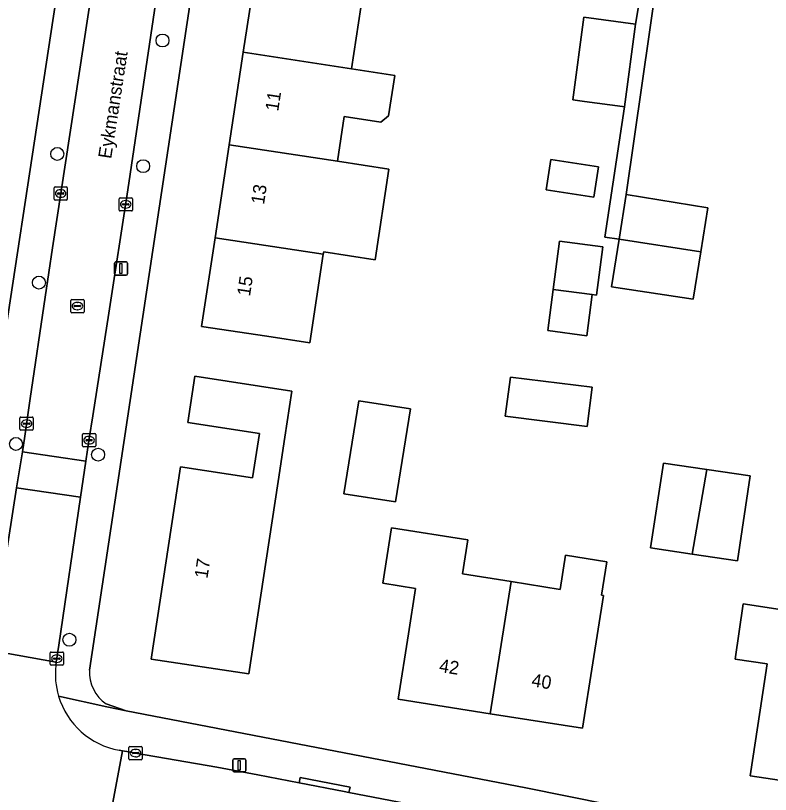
# Model space of a CAD drawing. Extents: x 161483 to 162250, y 379484 to 380833.
# Drawn here: x 161821 to 161877.9, y 380425.9 to 380484.6 of the extents above; entities that cross this region are included whole.
import ezdxf

# ---------------------------------------------------------------- set-up
doc = ezdxf.new("R2010")
doc.units = 0
for name, color, linetype in [('IMGEO_Boom', 7, 'Continuous'), ('IMGEO_Erf', 7, 'Continuous'), ('IMGEO_Kolk', 7, 'Continuous'), ('IMGEO_Lichtmast', 7, 'Continuous'), ('IMGEO_Openbare_ruimte_label', 7, 'Continuous'), ('IMGEO_Pand', 7, 'Continuous'), ('IMGEO_Pand_nummerreeks', 7, 'Continuous'), ('IMGEO_Rijbaan_lokaal_open', 7, 'Continuous'), ('IMGEO_Rioolput', 7, 'Continuous'), ('IMGEO_Voetpad_open', 7, 'Continuous')]:
    doc.layers.add(name, color=color, linetype=linetype)

msp = doc.modelspace()

# ---------------------------------------------------------------- linework, layer by layer
at = {"layer": 'IMGEO_Boom'}
for centre in [(161832.053, 380482.762), (161824.11, 380474.203), (161830.591, 380473.281), (161822.726, 380464.494), (161820.99, 380452.319), (161827.191, 380451.51), (161825.022, 380437.542)]:
    msp.add_circle(centre, 0.489, dxfattribs=at)
at = {"layer": 'IMGEO_Erf'}
for points in [[(161816.597, 380437.337), (161826.151, 380500)], [(161836.294, 380500), (161826.545, 380435.252)], [(161847.388, 380487.593), (161846.325, 380480.624), (161849.593, 380480.124), (161849.126, 380477.069), (161848.539, 380476.607), (161845.777, 380477.029), (161845.262, 380473.654), (161849.136, 380473.063), (161848.096, 380466.22), (161844.219, 380466.817), (161844.191, 380466.631), (161843.171, 380459.949), (161839.939, 380460.44), (161834.995, 380461.191), (161836.017, 380467.88), (161837.089, 380474.902), (161838.154, 380481.872), (161839.218, 380488.841)], [(161869.458, 380487.783), (161867.068, 380471.144), (161873.226, 380470.146), (161872.687, 380466.824), (161872.106, 380463.236), (161865.943, 380464.186), (161866.521, 380467.762), (161865.439, 380467.927), (161866.935, 380477.763), (161866.787, 380477.783), (161863.922, 380478.165), (161863.02, 380478.285), (161863.852, 380484.527), (161867.767, 380484.005), (161868.414, 380487.907)], [(161827.793, 380432.697), (161829.302, 380432.17), (161859.489, 380426.367), (161890.306, 380420.151)]]:
    msp.add_lwpolyline(points, dxfattribs=at)
for points in [[(161864.97, 380473.224), (161864.624, 380470.945), (161861.027, 380471.492), (161861.373, 380473.771)], [(161865.293, 380467.183), (161864.819, 380463.556), (161864.5, 380463.597), (161864.093, 380460.488), (161861.148, 380460.874), (161861.555, 380463.983), (161862.03, 380467.61)], [(161841.285, 380452.827), (161840.776, 380449.476), (161838.573, 380434.968), (161831.208, 380436.086), (161833.411, 380450.594), (161838.839, 380449.771), (161839.386, 380453.116), (161833.958, 380453.939), (161834.487, 380457.423), (161841.814, 380456.311)], [(161864.486, 380456.598), (161864.116, 380453.64), (161857.926, 380454.413), (161858.33, 380457.368)], [(161850.762, 380454.963), (161849.653, 380447.95), (161845.753, 380448.566), (161846.862, 380455.58)], [(161876.428, 380449.9), (161875.458, 380443.493), (161872.05, 380444.001), (161868.901, 380444.47), (161869.871, 380450.877), (161873.15, 380450.388)], [(161858.366, 380441.927), (161862.062, 380441.346), (161862.467, 380443.921), (161865.6, 380443.429), (161865.203, 380440.905), (161865.341, 380440.883), (161864.543, 380435.803), (161863.766, 380430.863), (161856.799, 380431.958), (161849.837, 380433.053), (161850.614, 380437.993), (161851.153, 380441.421), (161848.684, 380441.811), (161849.344, 380445.993), (161855.093, 380445.084), (161854.688, 380442.506)], [(161885.232, 380438.827), (161884.863, 380436.392), (161888.436, 380435.851), (161888.805, 380438.289), (161891.983, 380437.808), (161891.602, 380435.289), (161891.75, 380435.267), (161890.225, 380425.196), (161883.326, 380426.241), (161876.424, 380427.286), (161877.173, 380432.23), (161877.701, 380435.72), (161875.279, 380436.087), (161875.888, 380440.242)]]:
    msp.add_lwpolyline(points, close=True, dxfattribs=at)
msp.add_arc((161829.438, 380435.083), 2.898, 176.64999, 235.41677, dxfattribs=at)
at = {"layer": 'IMGEO_Kolk'}
for p, q in [((161823.864, 380470.791), (161823.864, 380471.643)), ((161823.939, 380471.717), (161824.791, 380471.717)), ((161824.352, 380471.497), (161824.377, 380471.497)), ((161824.865, 380471.643), (161824.865, 380470.791)), ((161824.123, 380471.211), (161824.123, 380471.223)), ((161824.561, 380471.174), (161824.163, 380471.174)), ((161824.166, 380471.26), (161824.564, 380471.26)), ((161824.375, 380470.937), (161824.35, 380470.937)), ((161824.607, 380471.223), (161824.607, 380471.211)), ((161828.849, 380470.898), (161829.701, 380470.898)), ((161824.791, 380470.717), (161823.939, 380470.717)), ((161828.774, 380469.972), (161828.774, 380470.824)), ((161829.033, 380470.392), (161829.033, 380470.404)), ((161829.471, 380470.355), (161829.073, 380470.355)), ((161829.076, 380470.441), (161829.474, 380470.441)), ((161829.262, 380470.678), (161829.287, 380470.678)), ((161829.517, 380470.404), (161829.517, 380470.392)), ((161829.775, 380470.824), (161829.775, 380469.972)), ((161829.701, 380469.898), (161828.849, 380469.898)), ((161829.285, 380470.118), (161829.26, 380470.118)), ((161821.293, 380453.424), (161821.293, 380454.276)), ((161821.368, 380454.35), (161822.22, 380454.35)), ((161821.552, 380453.844), (161821.552, 380453.856)), ((161821.99, 380453.807), (161821.592, 380453.807)), ((161821.595, 380453.893), (161821.993, 380453.893)), ((161821.781, 380454.13), (161821.806, 380454.13)), ((161822.036, 380453.856), (161822.036, 380453.844)), ((161822.294, 380454.276), (161822.294, 380453.424)), ((161822.22, 380453.35), (161821.368, 380453.35)), ((161821.804, 380453.57), (161821.779, 380453.57)), ((161826.007, 380452.174), (161826.007, 380453.026)), ((161826.082, 380453.1), (161826.934, 380453.1)), ((161826.309, 380452.643), (161826.707, 380452.643)), ((161826.495, 380452.88), (161826.52, 380452.88)), ((161827.008, 380453.026), (161827.008, 380452.174)), ((161826.934, 380452.1), (161826.082, 380452.1)), ((161826.266, 380452.594), (161826.266, 380452.606)), ((161826.704, 380452.557), (161826.306, 380452.557)), ((161826.518, 380452.32), (161826.493, 380452.32)), ((161826.75, 380452.606), (161826.75, 380452.594)), ((161823.574, 380435.692), (161823.574, 380436.544)), ((161823.649, 380436.618), (161824.501, 380436.618)), ((161823.876, 380436.161), (161824.274, 380436.161)), ((161824.062, 380436.398), (161824.087, 380436.398)), ((161824.575, 380436.544), (161824.575, 380435.692)), ((161824.501, 380435.618), (161823.649, 380435.618)), ((161823.833, 380436.112), (161823.833, 380436.124)), ((161824.271, 380436.075), (161823.873, 380436.075)), ((161824.085, 380435.838), (161824.06, 380435.838)), ((161824.317, 380436.124), (161824.317, 380436.112)), ((161829.522, 380428.564), (161829.522, 380429.416)), ((161829.597, 380429.49), (161830.449, 380429.49)), ((161830.01, 380429.27), (161830.035, 380429.27)), ((161830.523, 380429.416), (161830.523, 380428.564)), ((161829.781, 380428.984), (161829.781, 380428.996)), ((161830.219, 380428.947), (161829.821, 380428.947)), ((161829.824, 380429.033), (161830.222, 380429.033)), ((161830.033, 380428.71), (161830.008, 380428.71)), ((161830.265, 380428.996), (161830.265, 380428.984)), ((161830.449, 380428.49), (161829.597, 380428.49))]:
    msp.add_line(p, q, dxfattribs=at)
for points in [[(161823.864, 380470.791), (161823.864, 380471.643)], [(161823.939, 380471.717), (161824.791, 380471.717)], [(161824.865, 380471.643), (161824.865, 380470.791)], [(161828.849, 380470.898), (161829.701, 380470.898)], [(161824.791, 380470.717), (161823.939, 380470.717)], [(161828.774, 380469.972), (161828.774, 380470.824)], [(161829.775, 380470.824), (161829.775, 380469.972)], [(161829.701, 380469.898), (161828.849, 380469.898)], [(161821.293, 380453.424), (161821.293, 380454.276)], [(161821.368, 380454.35), (161822.22, 380454.35)], [(161822.294, 380454.276), (161822.294, 380453.424)], [(161822.22, 380453.35), (161821.368, 380453.35)], [(161826.007, 380452.174), (161826.007, 380453.026)], [(161826.082, 380453.1), (161826.934, 380453.1)], [(161827.008, 380453.026), (161827.008, 380452.174)], [(161826.934, 380452.1), (161826.082, 380452.1)], [(161823.574, 380435.692), (161823.574, 380436.544)], [(161823.649, 380436.618), (161824.501, 380436.618)], [(161824.575, 380436.544), (161824.575, 380435.692)], [(161824.501, 380435.618), (161823.649, 380435.618)], [(161829.522, 380428.564), (161829.522, 380429.416)], [(161829.597, 380429.49), (161830.449, 380429.49)], [(161830.523, 380429.416), (161830.523, 380428.564)], [(161830.449, 380428.49), (161829.597, 380428.49)]]:
    msp.add_lwpolyline(points, dxfattribs=at)
for centre, radius, start, end in [((161823.941, 380471.641), 0.0765, 91.55205, 178.44795), ((161823.941, 380471.641), 0.0765, 91.55205, 178.44795), ((161824.789, 380471.641), 0.0765, 1.55205, 88.44795), ((161824.789, 380471.641), 0.0765, 1.55205, 88.44795), ((161824.163, 380471.22), 0.0403, 85.87752, 175.75265), ((161824.16, 380471.21), 0.0366, 178.93798, 274.71019), ((161824.564, 380471.217), 0.043, 264.86636, 352.45326), ((161824.568, 380471.222), 0.0386, 1.73085, 96.63898), ((161828.851, 380470.822), 0.0765, 91.55205, 178.44795), ((161828.851, 380470.822), 0.0765, 91.55205, 178.44795), ((161829.699, 380470.822), 0.0765, 1.55205, 88.44795), ((161829.699, 380470.822), 0.0765, 1.55205, 88.44795), ((161823.941, 380470.793), 0.0765, 181.55205, 268.44795), ((161823.941, 380470.793), 0.0765, 181.55205, 268.44795), ((161824.789, 380470.793), 0.0765, 271.55205, 358.44795), ((161824.789, 380470.793), 0.0765, 271.55205, 358.44795), ((161829.073, 380470.401), 0.0403, 85.87752, 175.75265), ((161829.07, 380470.391), 0.0366, 178.93798, 274.71019), ((161829.474, 380470.398), 0.043, 264.86636, 352.45326), ((161829.478, 380470.403), 0.0386, 1.73085, 96.63898), ((161828.851, 380469.974), 0.0765, 181.55205, 268.44795), ((161828.851, 380469.974), 0.0765, 181.55205, 268.44795), ((161829.699, 380469.974), 0.0765, 271.55205, 358.44795), ((161829.699, 380469.974), 0.0765, 271.55205, 358.44795), ((161821.37, 380454.274), 0.0765, 91.55205, 178.44795), ((161821.37, 380454.274), 0.0765, 91.55205, 178.44795), ((161821.592, 380453.853), 0.0403, 85.87752, 175.75265), ((161821.589, 380453.843), 0.0366, 178.93798, 274.71019), ((161821.993, 380453.85), 0.043, 264.86636, 352.45326), ((161821.997, 380453.855), 0.0386, 1.73085, 96.63898), ((161822.218, 380454.274), 0.0765, 1.55205, 88.44795), ((161822.218, 380454.274), 0.0765, 1.55205, 88.44795), ((161821.37, 380453.426), 0.0765, 181.55205, 268.44795), ((161821.37, 380453.426), 0.0765, 181.55205, 268.44795), ((161822.218, 380453.426), 0.0765, 271.55205, 358.44795), ((161822.218, 380453.426), 0.0765, 271.55205, 358.44795), ((161826.084, 380453.024), 0.0765, 91.55205, 178.44795), ((161826.084, 380453.024), 0.0765, 91.55205, 178.44795), ((161826.306, 380452.603), 0.0403, 85.87752, 175.75265), ((161826.711, 380452.605), 0.0386, 1.73085, 96.63898), ((161826.932, 380453.024), 0.0765, 1.55205, 88.44795), ((161826.932, 380453.024), 0.0765, 1.55205, 88.44795), ((161826.084, 380452.176), 0.0765, 181.55205, 268.44795), ((161826.084, 380452.176), 0.0765, 181.55205, 268.44795), ((161826.303, 380452.593), 0.0366, 178.93798, 274.71019), ((161826.707, 380452.6), 0.043, 264.86636, 352.45326), ((161826.932, 380452.176), 0.0765, 271.55205, 358.44795), ((161826.932, 380452.176), 0.0765, 271.55205, 358.44795), ((161823.651, 380436.542), 0.0765, 91.55205, 178.44795), ((161823.651, 380436.542), 0.0765, 91.55205, 178.44795), ((161823.873, 380436.121), 0.0403, 85.87752, 175.75265), ((161824.278, 380436.123), 0.0386, 1.73085, 96.63898), ((161824.499, 380436.542), 0.0765, 1.55205, 88.44795), ((161824.499, 380436.542), 0.0765, 1.55205, 88.44795), ((161823.651, 380435.694), 0.0765, 181.55205, 268.44795), ((161823.651, 380435.694), 0.0765, 181.55205, 268.44795), ((161823.87, 380436.111), 0.0366, 178.93798, 274.71019), ((161824.274, 380436.118), 0.043, 264.86636, 352.45326), ((161824.499, 380435.694), 0.0765, 271.55205, 358.44795), ((161824.499, 380435.694), 0.0765, 271.55205, 358.44795), ((161829.599, 380429.414), 0.0765, 91.55205, 178.44795), ((161829.599, 380429.414), 0.0765, 91.55205, 178.44795), ((161830.447, 380429.414), 0.0765, 1.55205, 88.44795), ((161830.447, 380429.414), 0.0765, 1.55205, 88.44795), ((161829.599, 380428.566), 0.0765, 181.55205, 268.44795), ((161829.599, 380428.566), 0.0765, 181.55205, 268.44795), ((161829.821, 380428.993), 0.0403, 85.87752, 175.75265), ((161829.818, 380428.983), 0.0366, 178.93798, 274.71019), ((161830.222, 380428.99), 0.043, 264.86636, 352.45326), ((161830.226, 380428.995), 0.0386, 1.73085, 96.63898), ((161830.447, 380428.566), 0.0765, 271.55205, 358.44795), ((161830.447, 380428.566), 0.0765, 271.55205, 358.44795)]:
    msp.add_arc(centre, radius, start, end, dxfattribs=at)
for centre, major_axis, ratio, start_param, end_param in [((161824.351, 380471.217), (-0.387, 0.002), 0.722429, 4.712389, 7.853982), ((161824.376, 380471.217), (-0.39, 0.002), 0.717154, 1.570796, 4.712389), ((161829.261, 380470.398), (-0.387, 0.002), 0.722429, 4.712389, 7.853982), ((161829.286, 380470.398), (-0.39, 0.002), 0.717154, 1.570796, 4.712389), ((161821.78, 380453.85), (-0.387, 0.002), 0.722429, 4.712389, 7.853982), ((161821.805, 380453.85), (-0.39, 0.002), 0.717154, 1.570796, 4.712389), ((161826.494, 380452.6), (-0.387, 0.002), 0.722429, 4.712389, 7.853982), ((161826.519, 380452.6), (-0.39, 0.002), 0.717154, 1.570796, 4.712389), ((161824.061, 380436.118), (-0.387, 0.002), 0.722429, 4.712389, 7.853982), ((161824.086, 380436.118), (-0.39, 0.002), 0.717154, 1.570796, 4.712389), ((161830.009, 380428.99), (-0.387, 0.002), 0.722429, 4.712389, 7.853982), ((161830.034, 380428.99), (-0.39, 0.002), 0.717154, 1.570796, 4.712389)]:
    msp.add_ellipse(centre, major_axis=major_axis, ratio=ratio, start_param=start_param, end_param=end_param, dxfattribs=at)
at = {"layer": 'IMGEO_Lichtmast'}
for p, q in [((161828.416, 380465.15), (161828.416, 380465.95)), ((161828.416, 380465.95), (161828.416, 380465.15)), ((161828.516, 380466.05), (161829.306, 380466.05)), ((161829.306, 380466.05), (161828.516, 380466.05)), ((161829.406, 380465.95), (161829.406, 380465.15)), ((161829.406, 380465.15), (161829.406, 380465.95)), ((161829.306, 380465.05), (161828.516, 380465.05)), ((161828.516, 380465.05), (161829.306, 380465.05)), ((161837.456, 380428.568), (161838.246, 380428.568)), ((161838.246, 380428.568), (161837.456, 380428.568)), ((161837.356, 380427.668), (161837.356, 380428.468)), ((161837.356, 380428.468), (161837.356, 380427.668)), ((161838.346, 380428.468), (161838.346, 380427.668)), ((161838.346, 380427.668), (161838.346, 380428.468)), ((161838.246, 380427.568), (161837.456, 380427.568)), ((161837.456, 380427.568), (161838.246, 380427.568))]:
    msp.add_line(p, q, dxfattribs=at)
for points in [[(161828.836, 380465.925), (161828.986, 380465.925), (161828.986, 380465.175), (161828.836, 380465.175), (161828.836, 380465.925)], [(161837.776, 380428.443), (161837.926, 380428.443), (161837.926, 380427.693), (161837.776, 380427.693), (161837.776, 380428.443)]]:
    msp.add_lwpolyline(points, dxfattribs=at)
for centre, start, end in [((161828.516, 380465.95), 90, 180), ((161828.516, 380465.95), 90, 180), ((161829.306, 380465.95), 0, 90), ((161829.306, 380465.95), 360, 90), ((161828.516, 380465.15), 180, 270), ((161828.516, 380465.15), 180, 270), ((161829.306, 380465.15), 270, 0), ((161829.306, 380465.15), 270, 0), ((161837.456, 380428.468), 90, 180), ((161837.456, 380428.468), 90, 180), ((161838.246, 380428.468), 0, 90), ((161838.246, 380428.468), 360, 90), ((161837.456, 380427.668), 180, 270), ((161837.456, 380427.668), 180, 270), ((161838.246, 380427.668), 270, 0), ((161838.246, 380427.668), 270, 0)]:
    msp.add_arc(centre, 0.1, start, end, dxfattribs=at)
at = {"layer": 'IMGEO_Pand'}
for points in [[(161847.388, 380487.593), (161839.218, 380488.841), (161838.154, 380481.872), (161846.325, 380480.624)], [(161867.767, 380484.005), (161863.852, 380484.527), (161863.02, 380478.285), (161863.922, 380478.165), (161866.787, 380477.783), (161866.935, 380477.763)], [(161845.262, 380473.654), (161845.777, 380477.029), (161848.539, 380476.607), (161849.126, 380477.069), (161849.593, 380480.124), (161846.325, 380480.624), (161838.154, 380481.872), (161837.089, 380474.902)], [(161845.262, 380473.654), (161837.089, 380474.902), (161836.017, 380467.88), (161844.191, 380466.631), (161844.219, 380466.817), (161848.096, 380466.22), (161849.136, 380473.063)], [(161864.97, 380473.224), (161861.373, 380473.771), (161861.027, 380471.492), (161864.624, 380470.945)], [(161872.687, 380466.824), (161873.226, 380470.146), (161867.068, 380471.144), (161866.521, 380467.762)], [(161836.017, 380467.88), (161834.995, 380461.191), (161839.939, 380460.44), (161843.171, 380459.949), (161844.191, 380466.631)], [(161861.555, 380463.983), (161864.5, 380463.597), (161864.819, 380463.556), (161865.293, 380467.183), (161862.03, 380467.61)], [(161872.687, 380466.824), (161866.521, 380467.762), (161865.943, 380464.186), (161872.106, 380463.236)], [(161864.093, 380460.488), (161864.5, 380463.597), (161861.555, 380463.983), (161861.148, 380460.874)], [(161838.573, 380434.968), (161840.776, 380449.476), (161841.285, 380452.827), (161841.814, 380456.311), (161834.487, 380457.423), (161833.958, 380453.939), (161839.386, 380453.116), (161838.839, 380449.771), (161833.411, 380450.594), (161831.208, 380436.086)], [(161864.486, 380456.598), (161858.33, 380457.368), (161857.926, 380454.413), (161864.116, 380453.64)], [(161845.753, 380448.566), (161849.653, 380447.95), (161850.762, 380454.963), (161846.862, 380455.58)], [(161872.05, 380444.001), (161873.15, 380450.388), (161869.871, 380450.877), (161868.901, 380444.47)], [(161872.05, 380444.001), (161875.458, 380443.493), (161876.428, 380449.9), (161873.15, 380450.388)], [(161858.366, 380441.927), (161854.688, 380442.506), (161855.093, 380445.084), (161849.344, 380445.993), (161848.684, 380441.811), (161851.153, 380441.421), (161850.614, 380437.993), (161849.837, 380433.053), (161856.799, 380431.958)], [(161858.366, 380441.927), (161856.799, 380431.958), (161863.766, 380430.863), (161864.543, 380435.803), (161865.341, 380440.883), (161865.203, 380440.905), (161865.6, 380443.429), (161862.467, 380443.921), (161862.062, 380441.346)], [(161883.326, 380426.241), (161884.863, 380436.392), (161885.232, 380438.827), (161875.888, 380440.242), (161875.279, 380436.087), (161877.701, 380435.72), (161877.173, 380432.23), (161876.424, 380427.286)]]:
    msp.add_lwpolyline(points, close=True, dxfattribs=at)
at = {"layer": 'IMGEO_Rijbaan_lokaal_open'}
for points in [[(161828.338, 380496.887), (161826.407, 380484.559), (161823.737, 380467.105), (161823.193, 380463.396), (161822.073, 380455.75), (161821.655, 380452.898), (161821.471, 380451.732), (161826.274, 380451.023), (161826.524, 380452.721), (161826.792, 380454.443), (161827.998, 380462.196), (161829.443, 380471.483), (161833.095, 380496.033)], [(161823.996, 380435.596), (161824.035, 380435.858), (161819.103, 380436.729)], [(161812.858, 380432.129), (161812.021, 380432.261), (161810.928, 380426.326), (161815.614, 380425.462), (161824.261, 380423.937), (161827.932, 380423.249), (161829.039, 380429.157), (161828.78, 380429.201)], [(161852.93, 380424.718), (161846.13, 380426.028), (161845.779, 380426.096), (161842.358, 380426.75), (161839.254, 380427.343), (161836.142, 380427.922), (161830.023, 380428.99), (161829.999, 380428.994), (161829.519, 380429.076), (161829.039, 380429.157), (161827.932, 380423.249)]]:
    msp.add_lwpolyline(points, dxfattribs=at)
for points in [[(161826.274, 380451.023), (161821.471, 380451.732), (161821.041, 380449.005), (161825.871, 380448.293)], [(161825.871, 380448.293), (161821.041, 380449.005), (161819.425, 380438.762), (161819.217, 380437.373), (161819.103, 380436.729), (161824.035, 380435.858), (161824.225, 380437.133)]]:
    msp.add_lwpolyline(points, close=True, dxfattribs=at)
for centre, radius, start, end in [((161829.8, 380434.96), 5.838, 173.7463, 196.57972), ((161829.816, 380434.964), 5.856, 196.57267, 259.80529)]:
    msp.add_arc(centre, radius, start, end, dxfattribs=at)
at = {"layer": 'IMGEO_Rioolput'}
for p, q in [((161825.203, 380463.224), (161826.055, 380463.224)), ((161825.128, 380462.298), (161825.128, 380463.15)), ((161825.387, 380462.718), (161825.387, 380462.73)), ((161825.825, 380462.681), (161825.427, 380462.681)), ((161825.43, 380462.767), (161825.828, 380462.767)), ((161825.616, 380463.004), (161825.641, 380463.004)), ((161825.871, 380462.73), (161825.871, 380462.718)), ((161826.129, 380463.15), (161826.129, 380462.298)), ((161826.055, 380462.224), (161825.203, 380462.224)), ((161825.639, 380462.444), (161825.614, 380462.444))]:
    msp.add_line(p, q, dxfattribs=at)
for points in [[(161825.203, 380463.224), (161826.055, 380463.224)], [(161825.128, 380462.298), (161825.128, 380463.15)], [(161826.129, 380463.15), (161826.129, 380462.298)], [(161826.055, 380462.224), (161825.203, 380462.224)]]:
    msp.add_lwpolyline(points, dxfattribs=at)
for centre, radius, start, end in [((161825.205, 380463.148), 0.0765, 91.55205, 178.44795), ((161825.205, 380463.148), 0.0765, 91.55205, 178.44795), ((161826.053, 380463.148), 0.0765, 1.55205, 88.44795), ((161826.053, 380463.148), 0.0765, 1.55205, 88.44795), ((161825.427, 380462.727), 0.0403, 85.87752, 175.75265), ((161825.424, 380462.717), 0.0366, 178.93798, 274.71019), ((161825.828, 380462.724), 0.043, 264.86636, 352.45326), ((161825.832, 380462.729), 0.0386, 1.73085, 96.63898), ((161825.205, 380462.3), 0.0765, 181.55205, 268.44795), ((161825.205, 380462.3), 0.0765, 181.55205, 268.44795), ((161826.053, 380462.3), 0.0765, 271.55205, 358.44795), ((161826.053, 380462.3), 0.0765, 271.55205, 358.44795)]:
    msp.add_arc(centre, radius, start, end, dxfattribs=at)
for centre, major_axis, ratio, start_param, end_param in [((161825.615, 380462.724), (-0.387, 0.002), 0.722429, 4.712389, 7.853982), ((161825.64, 380462.724), (-0.39, 0.002), 0.717154, 1.570796, 4.712389)]:
    msp.add_ellipse(centre, major_axis=major_axis, ratio=ratio, start_param=start_param, end_param=end_param, dxfattribs=at)
at = {"layer": 'IMGEO_Voetpad_open'}
for points in [[(161833.742, 380549.787), (161829.859, 380524.323), (161829.741, 380523.547), (161829.598, 380522.608), (161826.151, 380500), (161816.597, 380437.337)], [(161841.512, 380549.76), (161841.397, 380549.092), (161841.013, 380546.566), (161839.074, 380534.593), (161838.629, 380531.844), (161837.587, 380525.413), (161836.396, 380517.62), (161833.702, 380500), (161833.095, 380496.033), (161829.443, 380471.483), (161827.998, 380462.196), (161826.792, 380454.443), (161826.524, 380452.721), (161826.274, 380451.023), (161825.871, 380448.293), (161824.225, 380437.133), (161824.035, 380435.858), (161823.996, 380435.596)], [(161826.545, 380435.252), (161836.294, 380500)], [(161819.103, 380436.729), (161819.217, 380437.373), (161819.425, 380438.762), (161821.041, 380449.005), (161821.471, 380451.732), (161821.655, 380452.898), (161822.073, 380455.75), (161823.193, 380463.396), (161823.737, 380467.105), (161826.407, 380484.559), (161828.338, 380496.887)], [(161868.414, 380487.907), (161867.767, 380484.005), (161866.935, 380477.763), (161865.439, 380467.927), (161866.521, 380467.762), (161867.068, 380471.144), (161869.458, 380487.783)], [(161859.489, 380426.367), (161829.302, 380432.17), (161827.851, 380432.49), (161824.204, 380433.294)], [(161824.204, 380433.294), (161827.851, 380432.49), (161829.302, 380432.17), (161827.793, 380432.697)], [(161828.78, 380429.201), (161829.039, 380429.157), (161829.519, 380429.076), (161829.999, 380428.994), (161830.023, 380428.99), (161836.142, 380427.922), (161839.254, 380427.343), (161842.358, 380426.75), (161842.435, 380427.145), (161846.208, 380426.413), (161846.13, 380426.028), (161852.93, 380424.718), (161860.325, 380423.269), (161865.358, 380422.291), (161865.362, 380422.29), (161865.433, 380422.643), (161872.091, 380421.307), (161872.022, 380420.961), (161877.699, 380419.808), (161884.32, 380418.397), (161889.222, 380417.373), (161890.653, 380417.163)], [(161890.306, 380420.151), (161859.489, 380426.367)]]:
    msp.add_lwpolyline(points, dxfattribs=at)
msp.add_lwpolyline([(161842.435, 380427.145), (161842.358, 380426.75), (161845.779, 380426.096), (161846.13, 380426.028), (161846.208, 380426.413)], close=True, dxfattribs=at)
for centre, radius, start, end in [((161829.8, 380434.96), 5.838, 173.7463, 196.57972), ((161829.438, 380435.083), 2.898, 176.64999, 235.41677), ((161829.816, 380434.964), 5.856, 196.57267, 259.80529)]:
    msp.add_arc(centre, radius, start, end, dxfattribs=at)

# ---------------------------------------------------------------- texts
at = {"layer": 'IMGEO_Openbare_ruimte_label'}
msp.add_text('Eykmanstraat', height=1, rotation=81.1972, dxfattribs=at).set_placement((161828.175, 380473.796))
at = {"layer": 'IMGEO_Pand_nummerreeks'}
for s, rotation, p in [('11', 81.31481, (161840.787, 380477.385)), ('13', 81.31481, (161839.713, 380470.351)), ('15', 81.31481, (161838.655, 380463.429)), ('17', 81.36575, (161835.442, 380442.121)), ('42', 351.06759, (161852.891, 380435.123)), ('40', 351.06476, (161859.862, 380434.027))]:
    msp.add_text(s, height=1, rotation=rotation, dxfattribs=at).set_placement(p)

doc.saveas('drawing.dxf')
